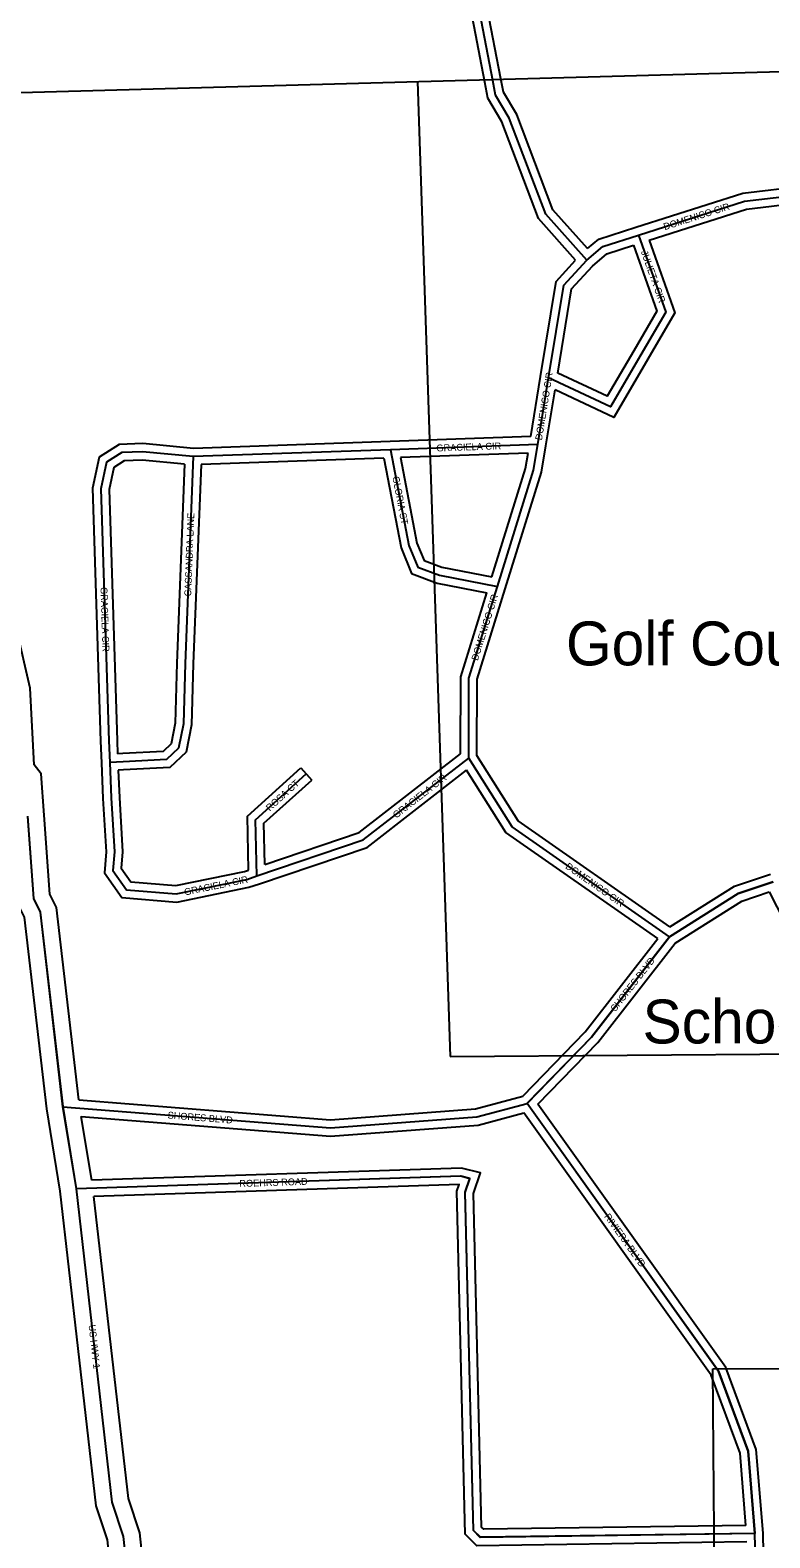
# Model space of a CAD drawing. Extents: x 418523 to 616617, y 1878279 to 2196743.
# Drawn here: x 554954 to 557650, y 1982252 to 1987751 of the extents above; entities that cross this region are included whole.
import ezdxf

# ---------------------------------------------------------------- set-up
doc = ezdxf.new("R2010")
doc.units = 0
for name, color, linetype in [('Level 1', 7, 'Continuous'), ('Level 13', 7, 'Continuous'), ('Level 14', 7, 'Continuous'), ('Level 31', 7, 'Continuous'), ('Level 32', 7, 'Continuous'), ('Level 34', 7, 'Continuous'), ('Level 57', 7, 'Continuous'), ('Level 8', 7, 'Continuous')]:
    doc.layers.add(name, color=color, linetype=linetype)

msp = doc.modelspace()

# ---------------------------------------------------------------- linework, layer by layer
at = {"layer": 'Level 1'}
for p, q in [((552451.43, 1987455.969), (557736.439, 1987601.436)), ((556365.837, 1987563.71), (556483.984, 1984007.449)), ((556483.984, 1984007.449), (566104.949, 1984084.796)), ((557441.34, 1982868.176), (560182.715, 1982875.733)), ((557464.018, 1980188.413), (557441.34, 1982868.176))]:
    msp.add_line(p, q, dxfattribs=at)
at = {"layer": 'Level 13'}
msp.add_line((555122.428, 1983524.359), (555073.131, 1983824.511), dxfattribs=at)
for points in [[(555073.131, 1983824.511), (554991.653, 1984533.502), (554966.73, 1984583.392), (554944.716, 1984883.47)], [(555686.555, 1979496.415), (555670.809, 1979771.381), (555637.679, 1979838.385), (555539.594, 1980630.695), (555514.599, 1980655.492), (555375.414, 1981498.101), (555294.06, 1982256.91), (555252.529, 1982382.122), (555122.428, 1983524.359)]]:
    msp.add_lwpolyline(points, dxfattribs=at)
at = {"layer": 'Level 14'}
for p, q in [((555062.979, 1983516.096), (555013.688, 1983816.219)), ((555178.002, 1983556.215), (555139.751, 1983789.116))]:
    msp.add_line(p, q, dxfattribs=at)
for points in [[(555004.546, 1984887.996), (554993.134, 1985038.841), (554968.569, 1985071.821), (554953.274, 1985350.883), (554904.08, 1985567.713), (554886.774, 1985892.59), (554860.508, 1985910.229), (554811.834, 1986426.903), (554790.139, 1986441.659), (554790.487, 1986567.375), (554761.701, 1986586.286), (554683.067, 1987254.117), (554616.803, 1987538.108)], [(555130.595, 1983850.036), (555050.054, 1984550.856), (555025.704, 1984599.602), (555004.556, 1984887.86)], [(555013.688, 1983816.218), (554933.25, 1984516.147), (554907.756, 1984567.181), (554888.324, 1984832.078)], [(555624.758, 1979526.071), (555611.604, 1979755.746), (555579.383, 1979820.913), (555482.598, 1980602.721), (555458.563, 1980626.565), (555315.938, 1981490.007), (555235.085, 1982244.121), (555193.617, 1982369.144), (555062.98, 1983516.096)], [(555745.904, 1979509.547), (555730.014, 1979787.016), (555695.976, 1979855.856), (555596.589, 1980658.67), (555570.634, 1980684.419), (555434.892, 1981506.194), (555353.034, 1982269.697), (555311.439, 1982395.1), (555185.997, 1983496.446)]]:
    msp.add_lwpolyline(points, dxfattribs=at)
at = {"layer": 'Level 31'}
for p, q in [((556803.742, 1986239.558), (556843.414, 1986482.737)), ((556803.742, 1986239.558), (556267.308, 1986220.648)), ((556267.308, 1986220.648), (555547.514, 1986195.341)), ((557617.113, 1981292.008), (557594.979, 1982267.392))]:
    msp.add_line(p, q, dxfattribs=at)
for points in [[(556639.854, 1987567.349), (556592.626, 1987813.672), (556567.614, 1987830.468), (556436.319, 1988539.228), (556378.501, 1988739.76), (556054.827, 1989265.762), (555738.657, 1989516.458), (555639.25, 1989700.377), (555490.191, 1990167.357), (555316.764, 1990768.231), (555233.833, 1990943.379), (555135.074, 1991360.766), (555101.934, 1991419.042), (554977.669, 1991786.315)], [(556982.235, 1986912.204), (556832.655, 1987079.526), (556700.066, 1987430.086), (556650.176, 1987513.499), (556639.854, 1987567.349)], [(557170.894, 1987003.7), (557557.883, 1987127.393), (557766.342, 1987151.926), (557974.246, 1986968.086)], [(556982.235, 1986912.204), (557040.734, 1986962.231), (557170.894, 1987003.7)], [(557170.894, 1987003.7), (557270.689, 1986722.688), (557179.549, 1986566.197)], [(556843.414, 1986482.737), (556898.567, 1986820.788), (556982.235, 1986912.204)], [(557179.549, 1986566.197), (557068.655, 1986376.668), (556843.414, 1986482.737)], [(556656.749, 1985722.11), (556788.264, 1986145.776), (556803.742, 1986239.558)], [(555547.514, 1986195.341), (555362.953, 1986212.938), (555287.135, 1986210.237), (555231.529, 1986174.751), (555210.962, 1986078.075), (555240.16, 1985159.035), (555243.749, 1985079.748)], [(555547.514, 1986195.341), (555518.171, 1985440.833), (555512.176, 1985220.474), (555494.489, 1985132.517), (555450.601, 1985091.181), (555292.607, 1985082.523), (555243.749, 1985079.748)], [(556267.308, 1986220.648), (556334.242, 1985871.721), (556366.699, 1985792.718), (556445.602, 1985763.047), (556656.749, 1985722.11)], [(556551.963, 1985096.177), (556552.752, 1985387.828), (556656.749, 1985722.11)], [(555779.972, 1984665.892), (556167.645, 1984797.205), (556551.963, 1985096.177)], [(557283.913, 1984443.982), (556709.889, 1984845.554), (556551.963, 1985096.177)], [(555243.749, 1985079.748), (555248.788, 1984950.636), (555260.619, 1984753.866), (555254.724, 1984686.241), (555304.334, 1984615.92), (555485.738, 1984600.876), (555743.142, 1984653.629), (555779.972, 1984665.892)], [(555779.972, 1984665.892), (555775.456, 1984871.006), (555959.894, 1985038.149)], [(557283.913, 1984443.982), (557534.299, 1984601.499), (557661.934, 1984644.431)], [(556765.53, 1983836.621), (556999.654, 1984077.819), (557283.913, 1984443.982)], [(555073.131, 1983824.511), (556048.371, 1983746.927), (556582.044, 1983787.297), (556765.53, 1983836.621)], [(557594.979, 1982267.392), (557570.722, 1982567.474), (557463.013, 1982859.416), (556765.53, 1983836.621)], [(557594.979, 1982267.392), (556594.389, 1982253.362), (556569.396, 1982278.522), (556539.426, 1983512.125), (556556.374, 1983562.264), (556523.089, 1983570.718), (555122.428, 1983524.359)]]:
    msp.add_lwpolyline(points, dxfattribs=at)
at = {"layer": 'Level 32'}
for p, q in [((556778.095, 1986268.673), (556813.805, 1986487.567)), ((556833.352, 1986234.727), (556866.62, 1986438.648)), ((556266.254, 1986250.63), (555548.416, 1986225.39)), ((556778.096, 1986268.673), (556266.251, 1986250.63)), ((556242.685, 1986189.763), (555576.411, 1986166.336)), ((556768.174, 1986208.285), (556303.371, 1986191.9)), ((555939.747, 1985060.379), (555980.039, 1985015.918)), ((557647.106, 1981292.689), (557624.954, 1982268.942))]:
    msp.add_line(p, q, dxfattribs=at)
for points in [[(556610.389, 1987561.7), (556565.517, 1987795.739), (556540.414, 1987812.596), (556407.086, 1988532.324), (556350.807, 1988727.52), (556032.046, 1989245.538), (555715.193, 1989496.776), (555611.524, 1989688.581), (555461.483, 1990158.636), (555288.613, 1990757.583), (555205.366, 1990933.396), (555106.87, 1991349.673), (555074.436, 1991406.707), (554962.417, 1991737.79)], [(556669.318, 1987572.997), (556619.734, 1987831.606), (556594.814, 1987848.34), (556465.55, 1988546.131), (556406.194, 1988752), (556077.609, 1989285.986), (555762.121, 1989536.14), (555666.978, 1989712.172), (555518.899, 1990176.08), (555344.917, 1990778.88), (555262.3, 1990953.361), (555163.279, 1991371.858), (555129.432, 1991431.377), (555012.914, 1991775.758)], [(556941.784, 1986912.44), (556806.569, 1987063.693), (556672.949, 1987416.977), (556621.709, 1987502.648), (556610.389, 1987561.701)], [(556985.042, 1986954.078), (556858.741, 1987095.36), (556727.182, 1987443.196), (556678.643, 1987524.351), (556669.318, 1987572.996)], [(557161.759, 1987032.276), (557551.504, 1987156.85), (557776.163, 1987183.289), (557967.932, 1987013.716)], [(557209.53, 1986984.551), (557564.262, 1987097.936), (557756.522, 1987120.562), (557954.373, 1986945.612)], [(556985.042, 1986954.078), (557025.847, 1986988.974), (557161.786, 1987032.285)], [(557003.129, 1986890.594), (557055.622, 1986935.488), (557152.339, 1986966.301)], [(557152.34, 1986966.301), (557237.761, 1986725.762), (557153.625, 1986581.296)], [(557209.53, 1986984.551), (557303.616, 1986719.614), (557205.474, 1986551.099)], [(556813.805, 1986487.567), (556870.398, 1986834.446), (556941.784, 1986912.439)], [(556876.669, 1986500.238), (556926.737, 1986807.131), (557003.128, 1986890.595)], [(557153.655, 1986581.348), (557056.616, 1986415.498), (556876.668, 1986500.238)], [(557205.444, 1986551.046), (557080.694, 1986337.838), (556866.62, 1986438.648)], [(555548.416, 1986225.39), (555363.847, 1986242.99), (555277.892, 1986239.928), (555204.798, 1986193.283), (555180.861, 1986080.759), (555210.182, 1985157.88), (555213.779, 1985078.391)], [(555516.435, 1986168.166), (555362.059, 1986182.886), (555296.379, 1986180.546), (555258.259, 1986156.22), (555241.063, 1986075.391), (555270.139, 1985160.189), (555272.348, 1985111.421)], [(556242.685, 1986189.762), (556305.346, 1985863.108), (556343.914, 1985769.235), (556437.409, 1985734.076), (556618.151, 1985699.033)], [(556303.371, 1986191.9), (556363.137, 1985880.332), (556389.485, 1985816.201), (556453.795, 1985792.018), (556636.068, 1985756.677)], [(556636.068, 1985756.678), (556758.999, 1986152.699), (556768.174, 1986208.285)], [(556685.4, 1985713.216), (556817.528, 1986138.855), (556833.342, 1986234.673)], [(555516.435, 1986168.166), (555488.186, 1985441.825), (555482.256, 1985223.864), (555466.961, 1985147.803), (555438.013, 1985120.536), (555290.936, 1985112.476), (555272.348, 1985111.421)], [(555576.411, 1986166.336), (555548.156, 1985439.841), (555542.096, 1985217.083), (555522.016, 1985117.231), (555463.189, 1985061.826), (555294.279, 1985052.569), (555274.878, 1985051.465)], [(556522.003, 1985110.878), (556522.764, 1985392.426), (556618.151, 1985699.032)], [(556581.988, 1985104.802), (556582.74, 1985383.229), (556685.395, 1985713.197)], [(555809.067, 1984707.421), (556153.223, 1984823.995), (556522.003, 1985110.878)], [(557284.794, 1984479.978), (556732.045, 1984866.667), (556581.988, 1985104.802)], [(555213.779, 1985078.391), (555218.822, 1984949.151), (555230.54, 1984754.27), (555223.884, 1984677.914), (555287.894, 1984587.18), (555487.546, 1984570.621), (555750.919, 1984624.598), (555789.449, 1984637.427)], [(555274.878, 1985051.466), (555278.754, 1984952.121), (555290.698, 1984753.461), (555285.565, 1984694.569), (555320.774, 1984644.66), (555483.93, 1984631.13), (555735.364, 1984682.659), (555749.492, 1984687.362)], [(555749.492, 1984687.362), (555745.161, 1984884.04), (555939.747, 1985060.379)], [(555789.597, 1984637.477), (556182.068, 1984770.416), (556544.241, 1985052.159)], [(557240.881, 1984437.473), (556687.734, 1984824.441), (556544.241, 1985052.159)], [(555809.067, 1984707.421), (555805.751, 1984857.973), (555980.039, 1985015.918)], [(557284.794, 1984479.978), (557521.349, 1984628.796), (557652.369, 1984672.867)], [(557304.367, 1984421.406), (557547.25, 1984574.203), (557647.006, 1984607.756)], [(557647.006, 1984607.756), (557922.182, 1984070.232), (559641.399, 1984118.026)], [(556749.761, 1983863.446), (556976.973, 1984097.525), (557240.881, 1984437.473)], [(556804.488, 1983833.681), (557022.336, 1984058.113), (557304.367, 1984421.406)], [(555130.595, 1983850.035), (556048.429, 1983777.018), (556576.974, 1983817), (556749.76, 1983863.446)], [(557624.954, 1982268.942), (557600.294, 1982573.996), (557489.767, 1982873.571), (556804.488, 1983833.681)], [(555139.751, 1983789.116), (556048.312, 1983716.836), (556587.114, 1983757.594), (556753.21, 1983802.243)], [(557562.494, 1982296.939), (557541.151, 1982560.953), (557436.259, 1982845.259), (556753.21, 1983802.243)], [(557562.494, 1982296.939), (556606.7, 1982283.538), (556599.098, 1982291.191), (556569.547, 1983507.547), (556595.175, 1983583.362), (556526.349, 1983600.843), (555178.002, 1983556.215)], [(557565.662, 1982236.977), (556582.079, 1982223.186), (556539.694, 1982265.854), (556509.305, 1983516.703), (556517.353, 1983540.511), (555185.997, 1983496.446)]]:
    msp.add_lwpolyline(points, dxfattribs=at)
at = {"layer": 'Level 8'}
msp.add_lwpolyline([(557661.619, 1984644.896), (557534.617, 1984601.893), (557283.614, 1984443.886), (556999.614, 1984077.874), (556765.612, 1983836.866), (557462.646, 1982859.852), (557570.654, 1982567.846), (557594.659, 1982267.84), (556594.636, 1982253.826), (556569.635, 1982278.826), (556539.613, 1983511.855), (556556.612, 1983561.856), (556522.611, 1983570.856), (555122.579, 1983524.836), (555073.572, 1983824.843), (554991.558, 1984533.858), (554966.556, 1984583.86), (554944.55, 1984883.866)], dxfattribs=at)

# ---------------------------------------------------------------- texts
at = {"layer": 'Level 34'}
for s, height, rotation, p in [('DOMENICO CIR', 25, 17.724653, (557266.49, 1987021.135)), ('JULIETA CIR', 25, 289.550231, (557179.289, 1986942.71)), ('DOMENICO CIR', 25, 80.733433, (556818.72, 1986253.756)), ('GRACIELA CIR', 25, 2.0181, (556434.925, 1986214.052)), ('GLORIA ST', 24.9992, 280.8579, (556273.639, 1986121.31)), ('CASSANDRA LANE', 25, 87.771819, (555540.191, 1985685.417)), ('GRACIELA CIR', 24.99916, 271.818697, (555209.859, 1985719.206)), ('DOMENICO CIR', 25, 72.717942, (556584.966, 1985449.304)), ('GRACIELA CIR', 25, 37.879569, (556287.677, 1984874.747)), ('ROSA CT', 25, 42.182833, (555826.707, 1984900.584)), ('DOMENICO CIR', 25, 325.023531, (556902.248, 1984695.732)), ('GRACIELA CIR', 25, 11.581175, (555517.904, 1984594.711)), ('SHORES BLVD', 25, 52.176239, (557086.47, 1984169.27)), ('SHORES BLVD', 25, 355.450708, (555453.794, 1983781.691)), ('ROEHRS ROAD', 25, 1.894903, (555716.459, 1983531.516)), ('RIVIERA BLVD', 25, 305.516453, (557044.814, 1983423.818)), ('US HWY 1', 25, 276.496967, (555166.399, 1983027.871))]:
    msp.add_text(s, height=height, rotation=rotation, dxfattribs=at).set_placement(p)
at = {"layer": 'Level 57'}
for s, p in [('Golf Course', (556906.64, 1985434.085)), ('School', (557185.754, 1984055.038))]:
    msp.add_text(s, height=160, dxfattribs=at).set_placement(p)

doc.saveas('drawing.dxf')
